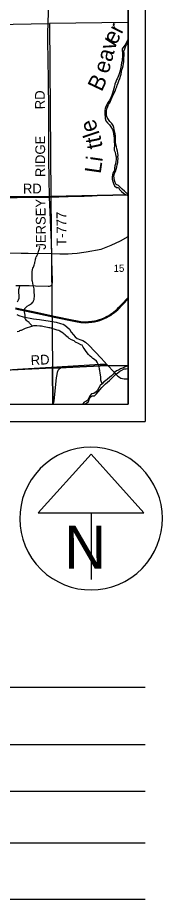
# Model space of a CAD drawing. Extents: x 0 to 34, y 0 to 22.
# Drawn here: x 8.26 to 9.1, y 11.22 to 16.35 of the extents above; entities that cross this region are included whole.
import ezdxf

# ---------------------------------------------------------------- set-up
doc = ezdxf.new("R2010")
doc.units = 0
for name, color, linetype in [('Default', 7, 'Continuous'), ('GM_X_Major_River', 7, 'Continuous'), ('GM_X_Major_River_Text', 7, 'Continuous'), ('GM_X_Minor_River', 7, 'Continuous'), ('GM_X_Rail_Line', 7, 'Continuous'), ('GM_X_Section', 7, 'Continuous'), ('GM_X_Section_Text', 7, 'Continuous'), ('GM_X_State_Route', 7, 'Continuous'), ('GM_X_Township_Road', 7, 'Continuous'), ('GM_X_Township_Road_Text', 7, 'Continuous'), ('SH_Cut_Line', 7, 'Continuous'), ('SH_Data', 7, 'Continuous')]:
    doc.layers.add(name, color=color, linetype=linetype)

msp = doc.modelspace()

# ---------------------------------------------------------------- linework, layer by layer
at = {"layer": 'Default'}
for points in [[(8.9, 15.317), (8.9, 16.3171), (8.4434, 16.3129), (8.4501, 15.3065)], [(8.9, 14.3247), (8.9, 15.317), (8.4501, 15.3065), (8.4592, 14.31), (8.7365, 14.322)], [(7.4967, 14.1), (8.4613, 14.1), (8.4592, 14.31), (7.496, 14.2624)], [(8.4613, 14.1), (8.9, 14.1), (8.9, 14.3247), (8.7365, 14.322), (8.4592, 14.31)]]:
    msp.add_lwpolyline(points, close=True, dxfattribs=at)
at = {"layer": 'GM_X_Major_River'}
for points in [[(8.9, 16.2209), (8.8906, 16.2034), (8.8858, 16.1931), (8.8755, 16.1793), (8.8662, 16.1654), (8.8656, 16.1556), (8.8666, 16.1423), (8.8675, 16.1328), (8.8666, 16.1188), (8.866, 16.1074), (8.8654, 16.0945), (8.861, 16.0845), (8.859, 16.0693), (8.858, 16.0587), (8.8563, 16.0492), (8.8542, 16.0389), (8.8494, 16.0263), (8.8455, 16.0144)], [(8.8522, 15.9929), (8.8562, 16.0055), (8.8591, 16.0173), (8.8611, 16.0303), (8.864, 16.0421), (8.8672, 16.0524), (8.8704, 16.0657), (8.8729, 16.079), (8.8742, 16.0885), (8.8748, 16.1003), (8.875, 16.1124), (8.8763, 16.1246), (8.8769, 16.1387), (8.8759, 16.1516), (8.8806, 16.1645), (8.885, 16.1771), (8.8908, 16.189), (8.9, 16.2019)], [(8.8455, 16.0144), (8.8426, 16.0045), (8.8374, 15.995), (8.8319, 15.9854), (8.8283, 15.9728), (8.8228, 15.9587), (8.8207, 15.9484), (8.8172, 15.9343), (8.8128, 15.9217), (8.8092, 15.908), (8.8053, 15.8961), (8.8016, 15.8866), (8.7946, 15.8747), (8.7891, 15.8629), (8.7824, 15.8533), (8.7758, 15.8399), (8.7707, 15.8299), (8.7659, 15.8177), (8.7646, 15.8056), (8.765, 15.7813), (8.7655, 15.7703), (8.7669, 15.7593), (8.7712, 15.7465), (8.7805, 15.7341), (8.7917, 15.7229), (8.7991, 15.7108), (8.8084, 15.6969), (8.8124, 15.6837), (8.8149, 15.6709), (8.8174, 15.6569), (8.8183, 15.6474), (8.8185, 15.6349), (8.8195, 15.6216), (8.8204, 15.6121), (8.8206, 15.6004), (8.8185, 15.5893), (8.819, 15.5764), (8.8238, 15.564), (8.827, 15.5504), (8.8307, 15.5368)], [(8.8412, 15.5441), (8.8394, 15.5582), (8.8377, 15.5707), (8.8341, 15.5831), (8.8316, 15.5956), (8.828, 15.6085), (8.827, 15.6217), (8.8269, 15.6312), (8.8271, 15.6445), (8.8265, 15.6566), (8.8244, 15.6714), (8.819, 15.696), (8.8162, 15.7081), (8.8126, 15.7202), (8.8052, 15.7318), (8.794, 15.7426), (8.7848, 15.7539), (8.7789, 15.7659), (8.7738, 15.778), (8.7736, 15.7913), (8.7745, 15.8042), (8.7762, 15.8164), (8.782, 15.8301), (8.7864, 15.8416), (8.7953, 15.8554), (8.8007, 15.8699), (8.8066, 15.8836), (8.8187, 15.9089), (8.8239, 15.9188), (8.8286, 15.9322), (8.8333, 15.9444), (8.8369, 15.9547), (8.8413, 15.9681), (8.846, 15.9799), (8.8522, 15.9929)], [(8.8307, 15.5368), (8.8301, 15.5347), (8.8296, 15.5218), (8.8275, 15.5096), (8.8263, 15.4967), (8.8227, 15.4841), (8.8203, 15.4716), (8.8202, 15.4587), (8.8129, 15.4464), (8.8086, 15.4323), (8.8069, 15.4201), (8.8075, 15.4072), (8.8119, 15.3948), (8.8156, 15.3816), (8.82, 15.3692), (8.8323, 15.3592), (8.8444, 15.3598), (8.8499, 15.3471), (8.8607, 15.3363), (8.8726, 15.3271), (8.8853, 15.3178), (8.8987, 15.3117), (8.9, 15.311)], [(8.9, 15.3208), (8.89, 15.3267), (8.8781, 15.3378), (8.8662, 15.3485), (8.8546, 15.3604), (8.8434, 15.3701), (8.8308, 15.377), (8.8245, 15.3886), (8.8205, 15.4007), (8.8184, 15.4131), (8.8166, 15.4271), (8.8209, 15.4397), (8.826, 15.4523), (8.8299, 15.4664), (8.8334, 15.4786), (8.837, 15.4912), (8.8405, 15.5042), (8.841, 15.5159), (8.8416, 15.5254), (8.8394, 15.539), (8.8412, 15.5441)], [(8.9, 14.3203), (8.8915, 14.3204), (8.8792, 14.3141), (8.8676, 14.3085), (8.8551, 14.3053), (8.8435, 14.2982), (8.8323, 14.2946), (8.82, 14.2845), (8.8126, 14.2748), (8.8033, 14.264), (8.7914, 14.2555), (8.7791, 14.2457), (8.7691, 14.2364), (8.7593, 14.2306), (8.7494, 14.2186), (8.7378, 14.2081), (8.7301, 14.1951), (8.7213, 14.182), (8.7132, 14.1713), (8.7001, 14.1619), (8.6873, 14.1597), (8.6765, 14.1493), (8.6719, 14.1374), (8.6661, 14.1233), (8.6545, 14.1151), (8.6444, 14.1111), (8.6348, 14.1)], [(8.6444, 14.1), (8.6449, 14.1009), (8.6569, 14.1064), (8.6692, 14.1154), (8.6739, 14.128), (8.6797, 14.1403), (8.6906, 14.1477), (8.7038, 14.1491), (8.7149, 14.1588), (8.7264, 14.1708), (8.7464, 14.1969), (8.7564, 14.2074), (8.7683, 14.2179), (8.7917, 14.2377), (8.8029, 14.2489), (8.814, 14.2612), (8.8266, 14.2732), (8.8393, 14.2826), (8.8524, 14.2912), (8.864, 14.2982), (8.8763, 14.3049), (8.8888, 14.3059), (8.9, 14.3079)]]:
    msp.add_lwpolyline(points, dxfattribs=at)
at = {"layer": 'GM_X_Minor_River'}
for points in [[(8.3443, 14.5535), (8.3269, 14.5706), (8.3234, 14.5747), (8.3176, 14.5783), (8.3134, 14.5821), (8.3083, 14.5869), (8.3041, 14.5921), (8.3017, 14.5962), (8.3004, 14.6027), (8.3001, 14.6194), (8.2996, 14.6236), (8.2988, 14.6277), (8.2975, 14.6365), (8.2966, 14.641), (8.2965, 14.6467), (8.2993, 14.6563), (8.3123, 14.6699), (8.3258, 14.6782), (8.3318, 14.6802), (8.34, 14.6857), (8.3426, 14.6899), (8.3478, 14.695), (8.3495, 14.7004), (8.3528, 14.7088), (8.3541, 14.7168), (8.3544, 14.7229), (8.3542, 14.7324), (8.3537, 14.7533), (8.3532, 14.7624), (8.3531, 14.7666), (8.3526, 14.7708), (8.3493, 14.7855), (8.348, 14.7931), (8.3459, 14.8003), (8.3447, 14.8052), (8.343, 14.8132), (8.3425, 14.8196), (8.3417, 14.8238), (8.3407, 14.8333), (8.341, 14.8382), (8.3409, 14.8432), (8.3411, 14.8515), (8.341, 14.858), (8.3419, 14.8694), (8.3443, 14.882), (8.346, 14.89), (8.3489, 14.8958), (8.3514, 14.9019), (8.3536, 14.9085), (8.3557, 14.9146), (8.3571, 14.9188), (8.3578, 14.923), (8.3609, 14.9387), (8.3619, 14.9433), (8.3637, 14.9494), (8.3658, 14.9555), (8.368, 14.9597), (8.3705, 14.9663), (8.3756, 14.9782), (8.3791, 14.9896), (8.3809, 14.9939), (8.3824, 14.9981), (8.3842, 15.0023), (8.3852, 15.0065), (8.3859, 15.0118), (8.3846, 15.0164)], [(8.7494, 14.2186), (8.7417, 14.2401), (8.7407, 14.2484), (8.7402, 14.2576), (8.7388, 14.2697), (8.7374, 14.2807), (8.7352, 14.2955), (8.734, 14.3015), (8.7305, 14.3201), (8.7289, 14.3246), (8.7254, 14.3333), (8.7194, 14.3442), (8.7152, 14.3502), (8.7047, 14.3595), (8.6955, 14.3657), (8.6882, 14.3709), (8.6793, 14.3791), (8.6693, 14.3887), (8.656, 14.4055), (8.6486, 14.4168), (8.6439, 14.4235), (8.6392, 14.431), (8.6318, 14.4423), (8.6253, 14.4456), (8.6111, 14.4529), (8.5928, 14.4612), (8.5858, 14.4671), (8.5709, 14.4729), (8.5567, 14.4821), (8.5517, 14.4877), (8.5429, 14.4928), (8.5359, 14.4991), (8.5336, 14.5032), (8.5278, 14.5073), (8.5212, 14.5129), (8.5116, 14.5191), (8.5025, 14.5239), (8.4975, 14.5272), (8.4864, 14.5304), (8.4818, 14.5329), (8.4696, 14.5353), (8.4582, 14.5385), (8.4513, 14.541), (8.4449, 14.5427), (8.4395, 14.5445), (8.4308, 14.5459), (8.4118, 14.5496), (8.395, 14.5527), (8.3908, 14.5533), (8.3855, 14.5536), (8.3696, 14.5552), (8.3548, 14.5552), (8.3488, 14.5543), (8.3443, 14.5535), (8.3314, 14.5501), (8.3258, 14.547), (8.3134, 14.5444), (8.3014, 14.5396), (8.2972, 14.5372), (8.2777, 14.5288), (8.2728, 14.5272), (8.2683, 14.5259), (8.2631, 14.5231), (8.2548, 14.5211)]]:
    msp.add_lwpolyline(points, dxfattribs=at)
at = {"layer": 'GM_X_Rail_Line'}
msp.add_lwpolyline([(5.5619, 14.1), (8.9, 14.1), (8.9, 17.3138), (8.2882, 17.3064), (7.4754, 17.3006), (7.4757, 17.0495), (7.4723, 16.4951), (7.4818, 15.827), (7.482, 15.8179), (7.4834, 15.2992), (7.3416, 15.297), (6.5709, 15.2859), (6.3575, 15.2833), (5.5569, 15.2761), (5.5579, 15.2049), (5.5588, 15.1747), (5.5581, 14.9676), (5.5583, 14.9347), (5.5595, 14.6439), (5.5615, 14.2414), (5.5608, 14.205)], close=True, dxfattribs=at)
for points in [[(8.2439, 14.6546), (8.3733, 14.6268), (8.4789, 14.6041), (8.5736, 14.584), (8.6037, 14.5783), (8.6247, 14.5754), (8.6498, 14.5736), (8.6693, 14.5742), (8.6896, 14.5765), (8.7049, 14.5788), (8.7223, 14.5828), (8.7348, 14.5863), (8.7487, 14.5912), (8.7631, 14.5971), (8.7761, 14.6036), (8.7901, 14.6111), (8.8006, 14.6178), (8.81, 14.6243), (8.8201, 14.6321), (8.8297, 14.6399), (8.8392, 14.6486), (8.8489, 14.6581), (8.8581, 14.6675), (8.8698, 14.6798), (8.9, 14.7112)], [(8.245, 14.6601), (8.3745, 14.6323), (8.4801, 14.6096), (8.5747, 14.5895), (8.6046, 14.5838), (8.6253, 14.581), (8.6499, 14.5792), (8.6689, 14.5799), (8.6888, 14.5821), (8.7038, 14.5844), (8.7209, 14.5883), (8.7331, 14.5917), (8.7467, 14.5964), (8.7608, 14.6023), (8.7735, 14.6086), (8.7873, 14.6159), (8.7974, 14.6225), (8.8067, 14.6289), (8.8166, 14.6365), (8.8259, 14.6442), (8.8353, 14.6527), (8.8449, 14.662), (8.854, 14.6714), (8.8658, 14.6836), (8.8959, 14.7151), (8.9, 14.7194)]]:
    msp.add_lwpolyline(points, dxfattribs=at)
at = {"layer": 'GM_X_Section'}
for points in [[(7.4857, 16.2946), (8.4434, 16.3129), (8.4501, 15.3065), (7.4868, 15.3017)], [(7.4868, 15.3017), (8.4501, 15.3065), (8.4592, 14.31), (7.496, 14.2624)]]:
    msp.add_lwpolyline(points, close=True, dxfattribs=at)
at = {"layer": 'GM_X_State_Route'}
for points in [[(7.7844, 15.0406), (7.8155, 15.0217), (7.8394, 15.0082), (7.8556, 15.0011), (7.8722, 14.9952), (7.8993, 14.9889), (7.9247, 14.9859), (7.9647, 14.9845), (8.1088, 14.9815), (8.2775, 14.978), (8.3183, 14.9772), (8.4559, 14.9747), (8.5031, 14.9735), (8.5319, 14.9737), (8.5511, 14.9742), (8.5747, 14.975), (8.6032, 14.9777), (8.6416, 14.9824), (8.6555, 14.9854), (8.743, 15.0009), (8.8016, 15.0236), (8.8553, 15.0495), (8.9, 15.0742)], [(8.4641, 14.1), (8.4655, 14.1051), (8.4687, 14.1185), (8.4835, 14.2536), (8.4864, 14.2733), (8.4887, 14.2855), (8.4933, 14.2967), (8.5042, 14.3089), (8.5186, 14.3187), (8.7377, 14.3317), (8.7478, 14.3321)], [(8.7478, 14.3321), (8.76, 14.3326), (8.7683, 14.3319), (8.7777, 14.3291)], [(8.7777, 14.3291), (8.8179, 14.2866), (8.8338, 14.2691), (8.8375, 14.2656)], [(8.8375, 14.2656), (8.8435, 14.2599), (8.8508, 14.2551), (8.8582, 14.251), (8.8674, 14.2487), (8.8768, 14.2475), (8.9, 14.2481)]]:
    msp.add_lwpolyline(points, dxfattribs=at)
at = {"layer": 'GM_X_Township_Road'}
for points in [[(8.4337, 16.2122), (8.4332, 16.2555), (8.4462, 16.6768)], [(8.4548, 15.0233), (8.4544, 15.0398), (8.4418, 15.3026), (8.4388, 15.5191), (8.4387, 15.6548), (8.4378, 15.8073), (8.4362, 15.9874), (8.4337, 16.2111), (8.4337, 16.2122)], [(7.4861, 15.2958), (7.5821, 15.2975), (7.841, 15.2997), (7.9594, 15.3011), (8.255, 15.301), (8.4418, 15.3026)], [(8.4418, 15.3026), (8.606, 15.308), (8.6446, 15.3086), (8.6904, 15.3101)], [(8.4567, 14.9356), (8.4559, 14.9747), (8.4548, 15.0233)], [(8.2672, 14.7891), (8.3235, 14.7893), (8.3615, 14.7879), (8.4343, 14.7858), (8.442, 14.7858), (8.4474, 14.7871), (8.452, 14.7894), (8.4558, 14.7929), (8.4577, 14.7979), (8.4593, 14.8058), (8.459, 14.8191), (8.4567, 14.9356)], [(8.2458, 14.7899), (8.2672, 14.7891), (8.2658, 14.7757), (8.263, 14.7641), (8.2624, 14.7469), (8.2643, 14.7327), (8.2643, 14.7215), (8.2636, 14.7141), (8.2596, 14.7049), (8.255, 14.6932)], [(8.2518, 14.6219), (8.264, 14.6159), (8.289, 14.6083), (8.3488, 14.5957), (8.3837, 14.5926), (8.4463, 14.5833), (8.4814, 14.5765), (8.5068, 14.5687), (8.5226, 14.564), (8.5325, 14.5593), (8.5431, 14.5499), (8.5586, 14.5365), (8.5694, 14.5187), (8.5819, 14.5029), (8.5913, 14.4918), (8.603, 14.4824), (8.6243, 14.4736), (8.6363, 14.4692), (8.6512, 14.4599), (8.6714, 14.4421), (8.7425, 14.3666), (8.7777, 14.3291)], [(8.1967, 14.3), (8.2878, 14.3059), (8.5186, 14.3187)]]:
    msp.add_lwpolyline(points, dxfattribs=at)
at = {"layer": 'SH_Cut_Line'}
msp.add_lwpolyline([(2.1, 14.1), (8.9, 14.1), (8.9, 17.3138), (8.2882, 17.3064), (7.4754, 17.3006)], dxfattribs=at)
at = {"layer": 'SH_Data'}
for p, q in [((9, 21), (9, 14)), ((8.9, 20.9), (8.9, 14.1)), ((2.1, 14.1), (8.9, 14.1)), ((2, 14), (9, 14)), ((8.6845, 13.8091), (8.3769, 13.4678)), ((8.9921, 13.4678), (8.6845, 13.8091)), ((8.3769, 13.4678), (8.9921, 13.4678)), ((8.6845, 13.4678), (8.6845, 13.0811)), ((8.6845, 13.4353), (8.6845, 13.4353)), ((8.6845, 13.4353), (8.6845, 13.4353)), ((7.75, 12.4553), (9, 12.4553)), ((9, 12.1207), (7.75, 12.1207)), ((9, 11.8491), (7.75, 11.8491)), ((9, 11.5491), (7.75, 11.5491)), ((9, 11.2223), (7.75, 11.2223))]:
    msp.add_line(p, q, dxfattribs=at)
msp.add_arc((8.6845, 13.4353), 0.4148, 129.7798, 129.7633, dxfattribs=at)

# ---------------------------------------------------------------- texts
at = {"layer": 'GM_X_Major_River_Text'}
for s, height, rotation, p in [('er', 0.09472, 62.7179, (8.8296, 16.1834)), ('eav', 0.09472, 74.7186, (8.7851, 16.0162)), ('B', 0.0947, 64.7181, (8.7458, 15.9116)), ('le', 0.09472, 108.723, (8.7353, 15.6702)), ('tt', 0.09472, 101.7217, (8.7529, 15.5936)), ('Li', 0.09472, 81.719, (8.7398, 15.436))]:
    msp.add_text(s, height=height, rotation=rotation, dxfattribs=at).set_placement(p)
at = {"layer": 'GM_X_Section_Text'}
msp.add_text('15', height=0.04186, rotation=0, dxfattribs=at).set_placement((8.8155, 14.869))
at = {"layer": 'GM_X_Township_Road_Text'}
for s, rotation, p in [('RD', 90.4937, (8.4157, 15.814)), ('RIDGE', 90.2166, (8.4174, 15.4198)), ('RD', 0.4937, (8.2879, 15.3241)), ('JERSEY', 90.5855, (8.4216, 14.9978)), ('T-777', 90.2804, (8.5407, 15.0197)), ('RD', 2.9612, (8.3344, 14.3265))]:
    msp.add_text(s, height=0.05682, rotation=rotation, dxfattribs=at).set_placement(p)
at = {"layer": 'SH_Data'}
msp.add_text('N', height=0.25, dxfattribs=at).set_placement((8.5292, 13.144))

doc.saveas('drawing.dxf')
